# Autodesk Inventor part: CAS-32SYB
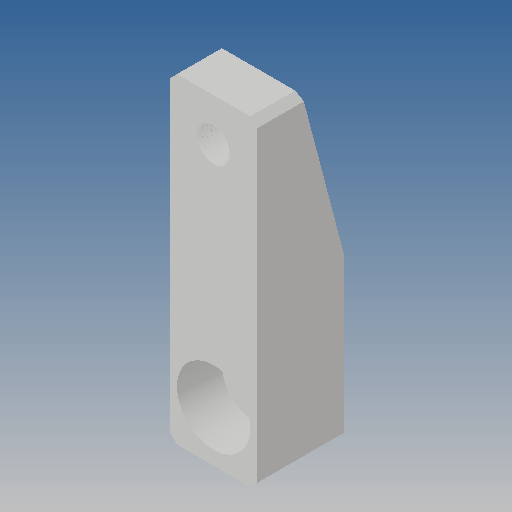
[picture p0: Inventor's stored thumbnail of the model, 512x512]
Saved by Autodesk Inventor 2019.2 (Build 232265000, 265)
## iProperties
Created: 2010-02
Part Number: CAS-32SYB
Material: Ogólny
Document SubType Name: Modeling
Designer: CADENGINEERING4
Density: 1 g/cm^3
Appearance: Domyślna
Author: CADENGINEERING4
Revision Number: 1LAST_VERSION
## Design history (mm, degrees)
feature "Baza1"
node "Bryła1"
